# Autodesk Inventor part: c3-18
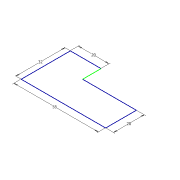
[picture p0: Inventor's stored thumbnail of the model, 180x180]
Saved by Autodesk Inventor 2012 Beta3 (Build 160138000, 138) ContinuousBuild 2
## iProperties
Created: 2011-02
Part Number: c3-18
Material: Default
Document SubType Name: Modeling
Designer: Beta-8540w
Density: 1 g/cm^3
Author: Beta-8540w
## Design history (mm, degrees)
sketch "Sketch1"
  geometry: L1 (0, 0)-(0, 32); L2 (0, 32)-(20, 32); L3 (0, 0)-(55, 0); L4 (55, 0)-(55, 20); L5 (55, 20)-(20, 20); L6 (20, 20)-(20, 32)
  constraints: 12 end point, 3 parallel, 2 perpendicular, 1 vertical
  dimensions: "d6" = 32 distance of L1.start L1.end; "d7" = 20 distance of L1.end L2.end; "d8" = 55 distance of L1.start L3.end; "d9" = 20 distance of L3.end L4.end
